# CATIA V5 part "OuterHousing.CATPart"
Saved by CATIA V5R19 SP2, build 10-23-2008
Part number: OuterHousing
Revision: ANY
Definition: UNKNOWN
Nomenclature: OuterHousing
Source: Unknown
Bounding box of the stored display mesh (mm): x -40.708 to 50.3, y 0 to 135, z -35.924 to 35.924
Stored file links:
  Z:\fausse table rondelle-20220905T211342Z-001\fausse table rondelle\OuterHousing.CATPart
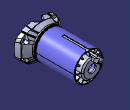
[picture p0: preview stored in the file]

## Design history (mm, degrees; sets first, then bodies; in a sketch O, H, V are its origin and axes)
AxisSystem1: origin (0, 0, 0), X (1, 0, 0), Y (0, 1, 0), Z (0, 0, 1)
Body1 "Schnitt-Linear austragen8" (main body)
  Solid1: solid without history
